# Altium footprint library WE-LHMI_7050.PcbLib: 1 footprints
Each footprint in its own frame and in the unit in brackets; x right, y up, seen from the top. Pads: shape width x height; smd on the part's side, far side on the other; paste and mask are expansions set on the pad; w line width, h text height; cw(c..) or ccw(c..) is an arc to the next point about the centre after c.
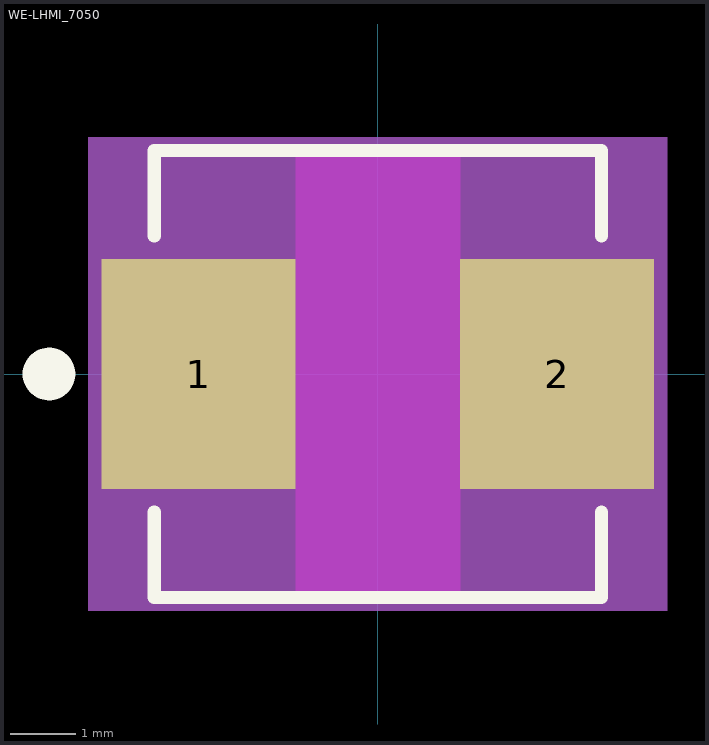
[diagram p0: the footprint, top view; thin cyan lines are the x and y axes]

## WE-LHMI_7050 [mm]
pads (2):
  rect 2.95x3.5 smd paste+0 mask+0.102: 1(-2.725,0) 2(2.725,0)
Top Overlay:
  circle w0.4: c-5,0 r0.2
  lines w0.2: -3.4,-2.1 -3.4,-3.4 3.4,-3.4 3.4,-2.1 ; -3.4,2.1 -3.4,3.4 3.4,3.4 3.4,2.1
Keep-Out Layer:
  region: 1.25,-3.3 -1.25,-3.3 -1.25,3.3 1.25,3.3
Assembly Top:
  circle w0.4: c-0.7,0 r0.1
  lines w0.1: -3.3,-3.3 3.3,-3.3 3.3,3.3 -3.3,3.3 -3.3,-3.3
Courtyard Top:
  region: 4.4,-3.6 -4.4,-3.6 -4.4,3.6 4.4,3.6
3D body "step_temp.STEP": height 3.3, standoff -3.3, extent -3.65,-4.7 3.65,0.1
